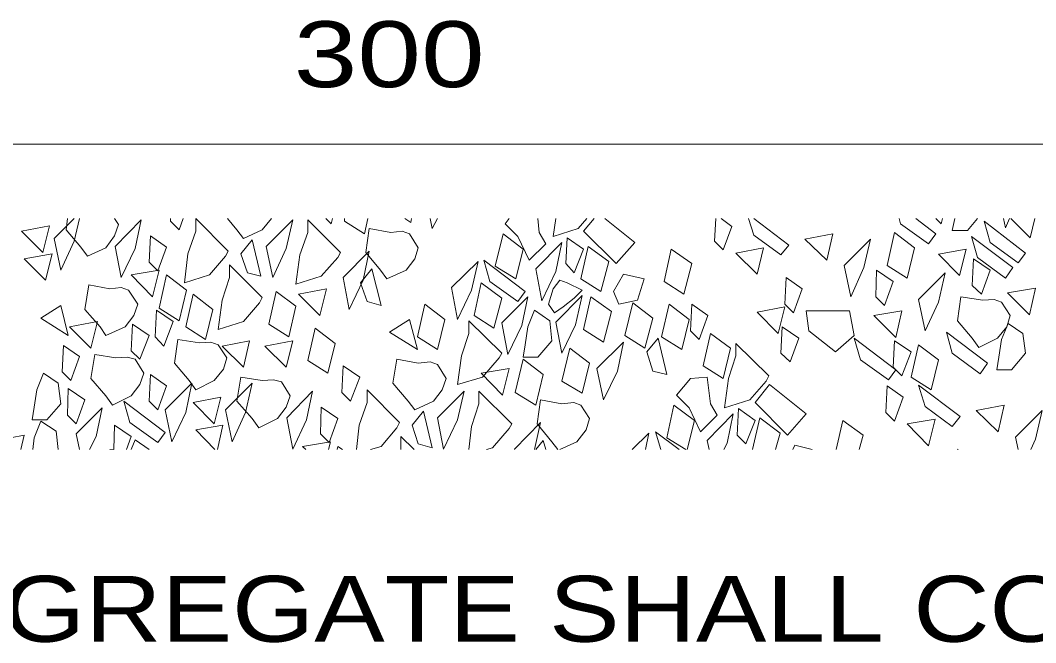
# Model space of a CAD drawing. Extents: x 312583 to 312854, y 144419 to 144597.
# Drawn here: x 312765.96 to 312777.68, y 144489.56 to 144496.74 of the extents above; entities that cross this region are included whole.
import ezdxf

# ---------------------------------------------------------------- set-up
doc = ezdxf.new("R2010")
doc.units = 0
doc.header["$LTSCALE"] = 0.3
doc.layers.add('2', color=7, linetype='Continuous', lineweight=13)

msp = doc.modelspace()

# ---------------------------------------------------------------- linework, layer by layer
at = {"layer": '2'}
for p, q in [((312758.6149, 144495.3122), (312781.6149, 144495.3122)), ((312766.3505, 144494.2236), (312766.5805, 144494.4536)), ((312768.3515, 144494.4536), (312768.4589, 144494.3232)), ((312769.7009, 144494.4229), (312769.7009, 144494.4536)), ((312774.3622, 144494.4536), (312774.4235, 144494.2619)), ((312776.1025, 144494.4536), (312776.1179, 144494.3922)), ((312767.0482, 144492.0692), (312767.0405, 144491.7856)), ((312766.6419, 144491.7856), (312766.6035, 144491.9696)), ((312767.9835, 144492.0156), (312768.2059, 144491.7856)), ((312773.6415, 144491.7856), (312773.4192, 144491.9236)), ((312777.4749, 144491.7856), (312777.4442, 144491.9312)), ((312767.2859, 144491.9006), (312767.2399, 144491.7856)), ((312767.4469, 144491.7856), (312767.2859, 144491.9006)), ((312769.2179, 144491.8239), (312769.2562, 144491.7856)), ((312772.0929, 144491.8776), (312772.1619, 144491.7856)), ((312773.9099, 144491.7856), (312773.8869, 144491.8929)), ((312774.8989, 144491.8392), (312774.8759, 144491.7856)), ((312775.0982, 144491.7856), (312774.8989, 144491.8392)), ((312770.3525, 144491.7932), (312770.3525, 144491.7856)), ((312771.6635, 144491.7856), (312771.6635, 144491.7932)), ((312776.7772, 144491.7932), (312776.7772, 144491.7856)), ((312776.7849, 144491.7856), (312776.7772, 144491.7932))]:
    msp.add_line(p, q, dxfattribs=at)
for points in [[(312766.6419, 144494.4536), (312766.5805, 144494.1929), (312766.4272, 144493.8556), (312766.3505, 144494.2236)], [(312766.5039, 144494.4536), (312766.4885, 144494.3232), (312766.6572, 144494.1239)], [(312766.6572, 144494.1239), (312766.7339, 144494.0166), (312766.9485, 144494.1162), (312767.0482, 144494.2542), (312767.0942, 144494.3846), (312767.0482, 144494.4536)], [(312767.6922, 144494.4536), (312767.6922, 144494.4229), (312767.7919, 144494.3232), (312767.8379, 144494.4536)], [(312768.4589, 144494.3232), (312768.5355, 144494.2236), (312768.7502, 144494.3232), (312768.8575, 144494.4536)], [(312769.4862, 144494.4536), (312769.5475, 144494.3922), (312769.5629, 144494.4536)], [(312769.9692, 144494.4536), (312769.9309, 144494.2772), (312769.7009, 144494.4229)], [(312770.4752, 144494.4536), (312770.4675, 144494.4076), (312770.3985, 144494.4536)], [(312770.7742, 144494.4536), (312770.7129, 144494.3386), (312770.6899, 144494.4536)], [(312771.8322, 144493.9706), (312771.7019, 144494.2466), (312771.5562, 144494.3922), (312771.6022, 144494.4536)], [(312771.9319, 144494.4536), (312771.9472, 144494.2926), (312772.0239, 144494.1622), (312771.8322, 144493.9706)], [(312772.1389, 144494.4536), (312772.1082, 144494.2466), (312772.3995, 144494.3386), (312772.4992, 144494.4536)], [(312772.5835, 144494.4536), (312772.4609, 144494.3079), (312772.8365, 144493.9322), (312773.0512, 144494.1776), (312772.7062, 144494.4536)], [(312773.9865, 144494.4536), (312773.9712, 144494.1929), (312774.0709, 144494.0932), (312774.1705, 144494.3616), (312774.0479, 144494.4536)], [(312774.4235, 144494.2619), (312774.7379, 144494.0319), (312774.8299, 144494.1469), (312774.4235, 144494.4536)], [(312776.1179, 144494.3922), (312776.4399, 144494.1622), (312776.5242, 144494.2772), (312776.2942, 144494.4536)], [(312776.5242, 144494.4536), (312776.5855, 144494.3922), (312776.6009, 144494.4536)], [(312776.7465, 144494.4536), (312776.7159, 144494.3156), (312776.8922, 144494.3156), (312777.0072, 144494.4536)], [(312777.3752, 144494.4536), (312777.3292, 144494.3462), (312777.3062, 144494.4536)], [(312777.3905, 144494.4536), (312777.6129, 144494.2312), (312777.6665, 144494.4536)], [(312769.9999, 144491.7856), (312770.1225, 144491.8239), (312770.3065, 144492.0386), (312770.3372, 144492.0999), (312769.9615, 144492.4756), (312769.9615, 144492.3299)], [(312771.3415, 144491.7856), (312771.4105, 144491.8086), (312771.6022, 144492.0309), (312771.6329, 144492.0846), (312771.2495, 144492.4602), (312771.2495, 144492.3146)], [(312769.9615, 144492.3299), (312769.8695, 144492.0692), (312769.8389, 144491.7856)], [(312771.2495, 144492.3146), (312771.1652, 144492.0539), (312771.1345, 144491.7856)], [(312772.1849, 144491.7856), (312772.3842, 144491.8776), (312772.4915, 144492.0156), (312772.5299, 144492.1459), (312772.4302, 144492.2992), (312772.3459, 144492.3299), (312772.2079, 144492.3146), (312771.9625, 144492.3606), (312771.9242, 144492.0846), (312772.0929, 144491.8776)], [(312773.4192, 144491.9236), (312773.5035, 144492.2992), (312773.7412, 144492.1229), (312773.6569, 144491.7856)], [(312766.6035, 144491.9696), (312766.9025, 144492.2686), (312766.8335, 144491.9389), (312766.7569, 144491.7856)], [(312773.8869, 144491.8929), (312774.1859, 144492.1996), (312774.1169, 144491.8622), (312774.0785, 144491.7856)], [(312774.4082, 144491.7856), (312774.4925, 144492.1536), (312774.7302, 144491.9772), (312774.6765, 144491.7856)], [(312777.4442, 144491.9312), (312777.7509, 144492.2379), (312777.6742, 144491.9082), (312777.6205, 144491.7856)], [(312766.1972, 144492.1152), (312766.1205, 144491.9236), (312766.1052, 144491.7856)], [(312766.3965, 144491.7856), (312766.3735, 144492.0002), (312766.1972, 144492.1152)], [(312767.1862, 144491.7856), (312767.2399, 144491.9389), (312767.0482, 144492.0692)], [(312768.2365, 144491.7856), (312768.2979, 144492.0692), (312767.9835, 144492.0156)], [(312771.6635, 144491.7932), (312771.9625, 144492.0999), (312771.8935, 144491.7856)], [(312775.3742, 144491.7856), (312775.4509, 144492.1229), (312775.6885, 144491.9542), (312775.6425, 144491.7856)], [(312765.9672, 144491.7856), (312766.0055, 144491.9542), (312765.6835, 144491.8929)], [(312770.5059, 144491.7856), (312770.3525, 144491.9389), (312770.3525, 144491.7932)], [(312773.0205, 144491.7856), (312773.2122, 144491.9772), (312773.1739, 144491.7856)], [(312773.5649, 144491.7856), (312773.2889, 144491.9926), (312773.3502, 144491.7856)], [(312769.5169, 144491.7856), (312769.5399, 144491.8776), (312769.2179, 144491.8239)], [(312769.6165, 144491.7856), (312769.6242, 144491.8239), (312769.6779, 144491.7856)], [(312772.0239, 144491.7856), (312771.9932, 144491.8929), (312771.9089, 144491.7856)], [(312767.0329, 144491.7856), (312767.0405, 144491.7932), (312766.9945, 144491.7856)]]:
    msp.add_lwpolyline(points, dxfattribs=at)
for points in [[(312767.0559, 144494.1316), (312767.3549, 144494.4382), (312767.2859, 144494.1086), (312767.1249, 144493.7712)], [(312767.9835, 144494.3079), (312767.8915, 144494.0472), (312767.8532, 144493.7099), (312768.1445, 144493.8019), (312768.3285, 144494.0166), (312768.3592, 144494.0779), (312767.9835, 144494.4536)], [(312768.7962, 144494.1316), (312769.1029, 144494.4382), (312769.0262, 144494.1086), (312768.8729, 144493.7712)], [(312769.2792, 144494.2926), (312769.1872, 144494.0319), (312769.1412, 144493.6946), (312769.4325, 144493.7866), (312769.6242, 144494.0012), (312769.6549, 144494.0626), (312769.2792, 144494.4382)], [(312777.1529, 144494.1776), (312777.4749, 144493.9399), (312777.5592, 144494.0549), (312777.0839, 144494.4229)], [(312765.9749, 144494.3079), (312766.2202, 144494.0626), (312766.2969, 144494.3692)], [(312770.1149, 144493.8556), (312770.1915, 144493.7559), (312770.4139, 144493.8556), (312770.5135, 144493.9859), (312770.5519, 144494.1162), (312770.4522, 144494.2772), (312770.3679, 144494.3079), (312770.2375, 144494.2926), (312769.9845, 144494.3386), (312769.9462, 144494.0626)], [(312771.4412, 144493.9016), (312771.5332, 144494.2772), (312771.7632, 144494.1009), (312771.6789, 144493.7559)], [(312775.0139, 144494.2159), (312775.2669, 144493.9706), (312775.3359, 144494.2772)], [(312775.9645, 144493.9092), (312776.0489, 144494.2926), (312776.2789, 144494.1162), (312776.1945, 144493.7636)], [(312767.4622, 144494.2542), (312767.4469, 144493.9476), (312767.5465, 144493.8479), (312767.6462, 144494.1239)], [(312768.5049, 144494.0472), (312768.5815, 144493.8249), (312768.7349, 144493.7866), (312768.6352, 144494.2082)], [(312771.9089, 144493.8709), (312772.2079, 144494.1776), (312772.1389, 144493.8402), (312771.9779, 144493.5029)], [(312772.2692, 144494.2312), (312772.2539, 144493.9322), (312772.3535, 144493.8249), (312772.4609, 144494.1009)], [(312775.4662, 144493.9092), (312775.7729, 144494.2159), (312775.6962, 144493.8862), (312775.5429, 144493.5489)], [(312777.0072, 144494.0012), (312777.3292, 144493.7636), (312777.4135, 144493.8862), (312776.9382, 144494.2466)], [(312766.0055, 144493.9859), (312766.2509, 144493.7406), (312766.3275, 144494.0472)], [(312769.6855, 144493.7712), (312769.9845, 144494.0779), (312769.9155, 144493.7406), (312769.7545, 144493.4032)], [(312772.4302, 144493.7559), (312772.5145, 144494.1316), (312772.7522, 144493.9552), (312772.6602, 144493.6102)], [(312773.3885, 144493.7252), (312773.4729, 144494.1009), (312773.7105, 144493.9322), (312773.6185, 144493.5796)], [(312774.2165, 144494.0549), (312774.4619, 144493.8096), (312774.5385, 144494.1162)], [(312776.5549, 144494.0396), (312776.8002, 144493.7942), (312776.8769, 144494.1009)], [(312768.3745, 144493.7712), (312768.2902, 144493.5106), (312768.2442, 144493.1732), (312768.5355, 144493.2652), (312768.7195, 144493.4799), (312768.7502, 144493.5412), (312768.3745, 144493.9169)], [(312770.9352, 144493.6562), (312771.2419, 144493.9552), (312771.1652, 144493.6256), (312771.0042, 144493.2882)], [(312771.3799, 144493.7252), (312771.7019, 144493.4952), (312771.7862, 144493.6102), (312771.3109, 144493.9706)], [(312776.9612, 144493.9859), (312776.9459, 144493.6792), (312777.0532, 144493.5796), (312777.1529, 144493.8556)], [(312767.2399, 144493.8019), (312767.4852, 144493.5489), (312767.5619, 144493.8556)], [(312767.5619, 144493.4186), (312767.6462, 144493.8019), (312767.8762, 144493.6256), (312767.7919, 144493.2729)], [(312769.8849, 144493.7099), (312769.9615, 144493.4952), (312770.1225, 144493.4492), (312770.0152, 144493.8709)], [(312772.9209, 144493.8096), (312772.8059, 144493.6102), (312772.8672, 144493.4646), (312773.0819, 144493.5106), (312773.1585, 144493.7559)], [(312775.8419, 144493.8556), (312775.8342, 144493.5489), (312775.9339, 144493.4492), (312776.0335, 144493.7252)], [(312776.3249, 144493.5182), (312776.6315, 144493.8249), (312776.5549, 144493.4876), (312776.4015, 144493.1579)], [(312766.8795, 144493.2039), (312766.9485, 144493.1042), (312767.1709, 144493.2039), (312767.2705, 144493.3342), (312767.3165, 144493.4646), (312767.2092, 144493.6256), (312767.1249, 144493.6562), (312766.9945, 144493.6409), (312766.7492, 144493.6869), (312766.7032, 144493.4032)], [(312771.1959, 144493.3342), (312771.2802, 144493.7099), (312771.5179, 144493.5336), (312771.4259, 144493.1886)], [(312772.2692, 144493.7099), (312772.1849, 144493.7406), (312772.1082, 144493.6409), (312772.0545, 144493.4646), (312772.1235, 144493.3649), (312772.2232, 144493.4339), (312772.3535, 144493.5336), (312772.4455, 144493.6256)], [(312774.7992, 144493.7712), (312774.7839, 144493.4646), (312774.8835, 144493.3649), (312774.9832, 144493.6409)], [(312767.8685, 144493.2039), (312767.9529, 144493.5796), (312768.1829, 144493.4032), (312768.0985, 144493.0582)], [(312768.8269, 144493.2346), (312768.9112, 144493.6102), (312769.1412, 144493.4416), (312769.0569, 144493.0889)], [(312769.1719, 144493.5796), (312769.4172, 144493.3342), (312769.4939, 144493.6409)], [(312772.1389, 144493.2576), (312772.4455, 144493.5642), (312772.3689, 144493.2269), (312772.2079, 144492.8972)], [(312777.3522, 144493.5949), (312777.6052, 144493.3419), (312777.6742, 144493.6486)], [(312766.1972, 144493.3036), (312766.5115, 144493.1042), (312766.4272, 144493.4492)], [(312770.5442, 144493.0889), (312770.6285, 144493.4646), (312770.8585, 144493.2882), (312770.7742, 144492.9432)], [(312771.5179, 144493.2499), (312771.8169, 144493.5489), (312771.7479, 144493.2192), (312771.5869, 144492.8819)], [(312772.4609, 144493.1732), (312772.5452, 144493.5489), (312772.7829, 144493.3802), (312772.6909, 144493.0276)], [(312772.9362, 144493.1042), (312773.0282, 144493.4799), (312773.2582, 144493.3036), (312773.1662, 144492.9586)], [(312773.3579, 144493.0889), (312773.4499, 144493.4646), (312773.6799, 144493.2882), (312773.5955, 144492.9432)], [(312773.7105, 144493.4646), (312773.6952, 144493.1579), (312773.7949, 144493.0582), (312773.8945, 144493.3342)], [(312776.9459, 144493.0736), (312777.0225, 144492.9662), (312777.2372, 144493.0736), (312777.3445, 144493.2039), (312777.3829, 144493.3342), (312777.2832, 144493.4876), (312777.1989, 144493.5182), (312777.0685, 144493.5106), (312776.8155, 144493.5489), (312776.7772, 144493.2729)], [(312767.5312, 144493.3956), (312767.5159, 144493.0889), (312767.6155, 144492.9816), (312767.7229, 144493.2652)], [(312771.8935, 144493.3956), (312771.8169, 144493.2039), (312771.7862, 144492.9969), (312771.7632, 144492.8512), (312771.9319, 144492.8512), (312772.0929, 144493.0429), (312772.0699, 144493.2729)], [(312774.4619, 144493.3726), (312774.7072, 144493.1272), (312774.7839, 144493.4339)], [(312775.0599, 144493.1579), (312775.3665, 144492.9126), (312775.5812, 144493.1042), (312775.5275, 144493.3879), (312775.0292, 144493.3879)], [(312775.8112, 144493.3342), (312776.0642, 144493.0812), (312776.1332, 144493.3879)], [(312766.5269, 144493.2039), (312766.7722, 144492.9586), (312766.8489, 144493.2652)], [(312767.2552, 144493.2346), (312767.2399, 144492.9279), (312767.3395, 144492.8282), (312767.4469, 144493.1042)], [(312770.2222, 144493.1426), (312770.5442, 144492.9432), (312770.4522, 144493.2882)], [(312771.1345, 144493.1272), (312771.0502, 144492.8666), (312771.0042, 144492.5369), (312771.2955, 144492.6212), (312771.4872, 144492.8436), (312771.5179, 144492.8972), (312771.1345, 144493.2729)], [(312777.3599, 144493.2422), (312777.2832, 144493.0582), (312777.2525, 144492.8512), (312777.2295, 144492.7056), (312777.3982, 144492.7056), (312777.5592, 144492.8972), (312777.5285, 144493.1272)], [(312769.2792, 144492.8129), (312769.3635, 144493.1886), (312769.5935, 144493.0122), (312769.5092, 144492.6672)], [(312773.8409, 144492.7516), (312773.9252, 144493.1272), (312774.1552, 144492.9586), (312774.0709, 144492.6059)], [(312774.7532, 144493.2039), (312774.7379, 144492.8972), (312774.8452, 144492.7976), (312774.9449, 144493.0736)], [(312776.7159, 144492.8972), (312777.0379, 144492.6596), (312777.1222, 144492.7822), (312776.6469, 144493.1426)], [(312766.4579, 144492.9892), (312766.4425, 144492.6826), (312766.5422, 144492.5829), (312766.6419, 144492.8589)], [(312767.9069, 144492.5829), (312767.9835, 144492.4756), (312768.1982, 144492.5829), (312768.3055, 144492.7132), (312768.3439, 144492.8436), (312768.2442, 144492.9969), (312768.1599, 144493.0276), (312768.0295, 144493.0199), (312767.7765, 144493.0582), (312767.7382, 144492.7822)], [(312768.2902, 144492.9816), (312768.5355, 144492.7362), (312768.6045, 144493.0429)], [(312768.7809, 144492.9816), (312769.0262, 144492.7362), (312769.1029, 144493.0429)], [(312772.6142, 144492.7209), (312772.9209, 144493.0276), (312772.8519, 144492.6902), (312772.6909, 144492.3606)], [(312773.1892, 144492.9126), (312773.2582, 144492.6902), (312773.4192, 144492.6519), (312773.3195, 144493.0736)], [(312774.2165, 144492.8666), (312774.1322, 144492.6059), (312774.0862, 144492.2686), (312774.3775, 144492.3606), (312774.5692, 144492.5752), (312774.5999, 144492.6366), (312774.2165, 144493.0122)], [(312775.6579, 144492.8206), (312775.9799, 144492.5906), (312776.0642, 144492.7056), (312775.5812, 144493.0736)], [(312776.0489, 144493.0429), (312776.0335, 144492.7362), (312776.1332, 144492.6366), (312776.2405, 144492.9126)], [(312776.2405, 144492.6212), (312776.3249, 144492.9969), (312776.5549, 144492.8206), (312776.4705, 144492.4756)], [(312766.9485, 144492.4066), (312767.0252, 144492.2992), (312767.2399, 144492.4066), (312767.3395, 144492.5369), (312767.3855, 144492.6672), (312767.2859, 144492.8282), (312767.1939, 144492.8512), (312767.0635, 144492.8436), (312766.8182, 144492.8819), (312766.7722, 144492.6059)], [(312772.2079, 144492.5752), (312772.2999, 144492.9586), (312772.5299, 144492.7822), (312772.4455, 144492.4372)], [(312769.6855, 144492.7516), (312769.6702, 144492.4449), (312769.7699, 144492.3452), (312769.8772, 144492.6212)], [(312770.4369, 144492.3452), (312770.5135, 144492.2456), (312770.7282, 144492.3452), (312770.8279, 144492.4756), (312770.8739, 144492.6059), (312770.7742, 144492.7669), (312770.6899, 144492.7976), (312770.5519, 144492.7822), (312770.3065, 144492.8282), (312770.2605, 144492.5522)], [(312771.6712, 144492.4449), (312771.7632, 144492.8282), (312771.9932, 144492.6519), (312771.9089, 144492.2992)], [(312766.2279, 144492.6672), (312766.1512, 144492.4756), (312766.1205, 144492.2762), (312766.0975, 144492.1306), (312766.2662, 144492.1306), (312766.4272, 144492.3146), (312766.3965, 144492.5522)], [(312767.4622, 144492.6519), (312767.4469, 144492.3452), (312767.5465, 144492.2456), (312767.6462, 144492.5216)], [(312768.6352, 144492.1459), (312768.7119, 144492.0386), (312768.9265, 144492.1459), (312769.0262, 144492.2762), (312769.0722, 144492.4066), (312768.9725, 144492.5676), (312768.8805, 144492.5906), (312768.7502, 144492.5829), (312768.5049, 144492.6212), (312768.4589, 144492.3452)], [(312771.2802, 144492.6672), (312771.5255, 144492.4142), (312771.6022, 144492.7209)], [(312773.8102, 144491.9926), (312773.6799, 144492.2686), (312773.5342, 144492.4142), (312773.6952, 144492.6059), (312773.8869, 144492.6212), (312773.9252, 144492.3146), (312774.0019, 144492.1842)], [(312767.6309, 144492.2456), (312767.9375, 144492.5522), (312767.8685, 144492.2149), (312767.7075, 144491.8776)], [(312768.3285, 144492.2456), (312768.6352, 144492.5522), (312768.5585, 144492.2149), (312768.4052, 144491.8776)], [(312774.6075, 144492.5369), (312774.4389, 144492.3299), (312774.8145, 144491.9542), (312775.0292, 144492.1996)], [(312775.9645, 144492.5216), (312775.9492, 144492.2149), (312776.0489, 144492.1152), (312776.1485, 144492.3912)], [(312776.4015, 144492.2839), (312776.7159, 144492.0539), (312776.8079, 144492.1689), (312776.3249, 144492.5292)], [(312766.5115, 144492.4909), (312766.5039, 144492.1842), (312766.6035, 144492.0846), (312766.7032, 144492.3606)], [(312767.9529, 144492.3299), (312768.1982, 144492.0846), (312768.2749, 144492.3912)], [(312769.0339, 144492.1536), (312769.3329, 144492.4602), (312769.2639, 144492.1306), (312769.1029, 144491.7932)], [(312770.7742, 144492.1536), (312771.0809, 144492.4602), (312771.0042, 144492.1306), (312770.8432, 144491.7932)], [(312767.2245, 144492.0999), (312767.5465, 144491.8699), (312767.6309, 144491.9849), (312767.1555, 144492.3452)], [(312769.4325, 144492.2762), (312769.4249, 144491.9696), (312769.5245, 144491.8699), (312769.6242, 144492.1459)], [(312776.9919, 144492.2379), (312777.2449, 144491.9926), (312777.3139, 144492.2992)], [(312770.4829, 144492.0692), (312770.5519, 144491.8546), (312770.7129, 144491.8086), (312770.6132, 144492.2302)], [(312774.2472, 144492.2609), (312774.2319, 144491.9542), (312774.3315, 144491.8546), (312774.4389, 144492.1229)], [(312776.1945, 144492.0846), (312776.4399, 144491.8316), (312776.5165, 144492.1382)]]:
    msp.add_lwpolyline(points, close=True, dxfattribs=at)

# ---------------------------------------------------------------- texts
for s, width, p in [('300 ', 1.3, (312769.1146, 144495.9688)), ('0.03 C.M. OF 19 MM AGGREGATE SHALL CONSIST OF', 1.2, (312752.2745, 144489.5689))]:
    msp.add_text(s, height=0.76, dxfattribs=dict(at, width=width)).set_placement(p)

doc.saveas('drawing.dxf')
